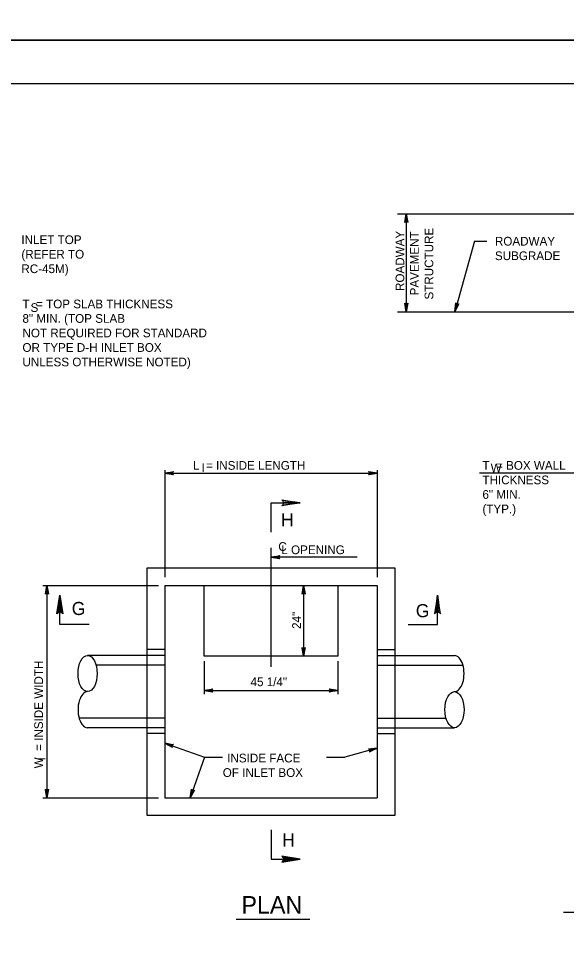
# Model space of a CAD drawing. Extents: x -6420 to 49575, y -4552 to 11624.
# Drawn here: x -5195 to -4576, y 6704 to 7751 of the extents above; entities that cross this region are included whole.
import ezdxf

# ---------------------------------------------------------------- set-up
doc = ezdxf.new("R2010")
doc.units = 0
doc.layers.add('1', color=7, linetype='Continuous')
doc.layers.add('PLT-BNDY', color=7, linetype='Continuous')

msp = doc.modelspace()

# ---------------------------------------------------------------- linework, layer by layer
at = {"layer": '1'}
for p, q in [((-4767, 7530), (-4533.9, 7530)), ((-4757.2, 7530), (-4757.2, 7419.5)), ((-4680.2, 7499.1), (-4702.2, 7419.5)), ((-4680.2, 7499.1), (-4666.2, 7499.1)), ((-4767, 7419.5), (-4533.9, 7419.5)), ((-5030, 7240.2), (-5030, 7119.4)), ((-5030, 7236.9), (-4790, 7236.9)), ((-4790, 7240.2), (-4790, 7119.4)), ((-4674.7, 7237.3), (-4479.3, 7237.3)), ((-4910, 7018), (-4910, 7152.5)), ((-4812.9, 7142), (-4910, 7142)), ((-5167.7, 7110), (-5037.3, 7110)), ((-5163.2, 7110), (-5163.2, 6870)), ((-5030, 7110), (-5030, 6870)), ((-5030, 7110), (-4790, 7110)), ((-4985.5, 7110), (-4834.6, 7110)), ((-4985.5, 7030), (-4985.5, 7110)), ((-4873.2, 7110), (-4873.2, 7030)), ((-4834.6, 7110), (-4834.6, 7030)), ((-4790, 7110), (-4790, 6870)), ((-5030, 7037.5), (-5050, 7037.5)), ((-4790, 7037.5), (-4770, 7037.5)), ((-5050, 7030.8), (-5117.3, 7030.8)), ((-5030, 7030.8), (-5050, 7030.8)), ((-4834.6, 7030), (-4985.5, 7030)), ((-4985.5, 7024.4), (-4985.5, 6987.1)), ((-4834.6, 7024.4), (-4834.6, 6987.1)), ((-4790, 7030.8), (-4770, 7030.8)), ((-4770, 7030.8), (-4702.8, 7030.8)), ((-5030, 7020), (-5107.7, 7020)), ((-4790, 7020), (-4693.2, 7020)), ((-4985.5, 6991.3), (-4834.6, 6991.3)), ((-5030, 6960), (-5126.9, 6960)), ((-4790, 6960), (-4712.3, 6960)), ((-5050, 6949.1), (-5117.3, 6949.1)), ((-5030, 6949.1), (-5050, 6949.1)), ((-5030, 6942.5), (-5050, 6942.5)), ((-4790, 6949.1), (-4770, 6949.1)), ((-4790, 6942.5), (-4770, 6942.5)), ((-4770, 6949.1), (-4702.8, 6949.1)), ((-5030, 6931.7), (-4985.3, 6915.8)), ((-4790, 6926), (-4826.8, 6915.8)), ((-4985.3, 6915.8), (-5001.5, 6870)), ((-4985.3, 6915.8), (-4964.9, 6915.8)), ((-4847.2, 6915.8), (-4826.8, 6915.8)), ((-5167.7, 6870), (-5037.3, 6870)), ((-5030, 6870), (-4790, 6870)), ((-4579.7, 6740.7), (-4459.5, 6740.7)), ((-4949.3, 6732.8), (-4866.2, 6732.8))]:
    msp.add_line(p, q, dxfattribs=at)
for points in [[(-3713.7, 5826.7), (-3713.7, 7677), (-6292.4, 7677), (-6292.4, 5826.7), (-3713.7, 5826.7), (-3713.7, 5913.1), (-4369.8, 5913.1), (-4369.8, 6125.3), (-3713.7, 6125.3), (-3713.7, 6220.4), (-4369.8, 6220.4), (-4369.8, 5826.7), (-4111.3, 5826.7), (-4111.3, 5913.1), (-4111.3, 5826.7), (-3858.7, 5826.7), (-3858.7, 5913.1), (-3858.7, 5872.7), (-3713.7, 5872.7)], [(-4757.2, 7530), (-4755.4, 7520.2), (-4755.9, 7521), (-4756.5, 7521.3), (-4757.2, 7521.5), (-4757.8, 7521.3), (-4758.5, 7521), (-4759, 7520.2), (-4757.2, 7530), (-4758.5, 7521), (-4757.8, 7521.3), (-4757.2, 7530), (-4757.2, 7521.5), (-4756.5, 7521.3), (-4757.2, 7530), (-4755.9, 7521)], [(-4757.2, 7419.5), (-4759, 7429.3), (-4758.5, 7428.6), (-4757.8, 7428.2), (-4757.2, 7428.1), (-4756.5, 7428.2), (-4755.9, 7428.6), (-4755.4, 7429.3), (-4757.2, 7419.5), (-4755.9, 7428.6), (-4756.5, 7428.2), (-4757.2, 7419.5), (-4757.2, 7428.1), (-4757.8, 7428.2), (-4757.2, 7419.5), (-4758.5, 7428.6)], [(-4702.2, 7419.5), (-4701.4, 7429.4), (-4701.1, 7428.6), (-4700.6, 7428), (-4699.9, 7427.7), (-4699.3, 7427.7), (-4698.6, 7427.9), (-4697.8, 7428.5), (-4702.2, 7419.5), (-4698.6, 7427.9), (-4699.3, 7427.7), (-4702.2, 7419.5), (-4699.9, 7427.7), (-4700.6, 7428), (-4702.2, 7419.5), (-4701.1, 7428.6)], [(-5030, 7236.9), (-5020.2, 7238.7), (-5020.6, 7238.5), (-5021, 7238.2), (-5021.2, 7237.9), (-5021.4, 7237.6), (-5021.4, 7237.2), (-5021.5, 7236.9), (-5021.4, 7236.6), (-5021.4, 7236.3), (-5021.2, 7235.9), (-5021, 7235.6), (-5020.6, 7235.3), (-5020.2, 7235.1), (-5030, 7236.9), (-5020.6, 7235.3), (-5021, 7235.6), (-5030, 7236.9), (-5021.2, 7235.9), (-5021.4, 7236.3), (-5030, 7236.9), (-5021.4, 7236.6), (-5021.5, 7236.9), (-5030, 7236.9), (-5021.4, 7237.2), (-5021.4, 7237.6), (-5030, 7236.9), (-5021.2, 7237.9), (-5021, 7238.2), (-5030, 7236.9), (-5020.6, 7238.5)], [(-4790, 7236.9), (-4799.8, 7235.1), (-4799.4, 7235.3), (-4799.1, 7235.6), (-4798.9, 7235.9), (-4798.7, 7236.3), (-4798.6, 7236.6), (-4798.6, 7236.9), (-4798.6, 7237.2), (-4798.7, 7237.6), (-4798.9, 7237.9), (-4799.1, 7238.2), (-4799.4, 7238.5), (-4799.8, 7238.7), (-4790, 7236.9), (-4799.4, 7238.5), (-4799.1, 7238.2), (-4790, 7236.9), (-4798.9, 7237.9), (-4798.7, 7237.6), (-4790, 7236.9), (-4798.6, 7237.2), (-4798.6, 7236.9), (-4790, 7236.9), (-4798.6, 7236.6), (-4798.7, 7236.3), (-4790, 7236.9), (-4798.9, 7235.9), (-4799.1, 7235.6), (-4790, 7236.9), (-4799.4, 7235.3)], [(-4910, 7170.3), (-4910, 7203.4), (-4877, 7203.4)], [(-4897, 7205.9), (-4896.2, 7204.5), (-4877, 7203.4), (-4897, 7205.9), (-4898, 7206.8), (-4877, 7203.4), (-4896.2, 7202.5), (-4896.9, 7201), (-4877, 7203.4), (-4898, 7200.1), (-4896.9, 7201)], [(-4910, 7142), (-4900.2, 7143.8), (-4900.6, 7143.5), (-4901, 7143.3), (-4901.2, 7143), (-4901.4, 7142.6), (-4901.4, 7142.3), (-4901.5, 7142), (-4901.4, 7141.6), (-4901.4, 7141.3), (-4901.2, 7141), (-4901, 7140.7), (-4900.6, 7140.4), (-4900.2, 7140.1), (-4910, 7142), (-4900.6, 7140.4), (-4901, 7140.7), (-4910, 7142), (-4901.2, 7141), (-4901.4, 7141.3), (-4910, 7142), (-4901.4, 7141.6), (-4901.5, 7142), (-4910, 7142), (-4901.4, 7142.3), (-4901.4, 7142.6), (-4910, 7142), (-4901.2, 7143), (-4901, 7143.3), (-4910, 7142), (-4900.6, 7143.5)], [(-5163.2, 7110), (-5161.4, 7100.2), (-5161.6, 7100.6), (-5161.9, 7100.9), (-5162.2, 7101.1), (-5162.6, 7101.3), (-5162.9, 7101.4), (-5163.2, 7101.4), (-5163.5, 7101.4), (-5163.9, 7101.3), (-5164.2, 7101.1), (-5164.5, 7100.9), (-5164.8, 7100.6), (-5165, 7100.2), (-5163.2, 7110), (-5164.8, 7100.6), (-5164.5, 7100.9), (-5163.2, 7110), (-5164.2, 7101.1), (-5163.9, 7101.3), (-5163.2, 7110), (-5163.5, 7101.4), (-5163.2, 7101.4), (-5163.2, 7110), (-5162.9, 7101.4), (-5162.6, 7101.3), (-5163.2, 7110), (-5162.2, 7101.1), (-5161.9, 7100.9), (-5163.2, 7110), (-5161.6, 7100.6)], [(-4873.2, 7110), (-4871.3, 7100.2), (-4871.6, 7100.6), (-4871.8, 7100.9), (-4872.2, 7101.1), (-4872.5, 7101.3), (-4872.8, 7101.4), (-4873.2, 7101.4), (-4873.5, 7101.4), (-4873.8, 7101.3), (-4874.1, 7101.1), (-4874.5, 7100.9), (-4874.7, 7100.6), (-4875, 7100.2), (-4873.2, 7110), (-4874.7, 7100.6), (-4874.5, 7100.9), (-4873.2, 7110), (-4874.1, 7101.1), (-4873.8, 7101.3), (-4873.2, 7110), (-4873.5, 7101.4), (-4873.2, 7101.4), (-4873.2, 7110), (-4872.8, 7101.4), (-4872.5, 7101.3), (-4873.2, 7110), (-4872.2, 7101.1), (-4871.8, 7100.9), (-4873.2, 7110), (-4871.6, 7100.6)], [(-5151.2, 7078.9), (-5149.8, 7079.6), (-5148.7, 7098.9), (-5151.2, 7078.9), (-5152.1, 7077.8), (-5148.7, 7098.9), (-5147.7, 7079.6), (-5146.3, 7078.9), (-5148.7, 7098.9), (-5145.3, 7077.8), (-5146.3, 7078.9)], [(-5115.6, 7065.8), (-5148.7, 7065.8), (-5148.7, 7098.9)], [(-4755.1, 7065.8), (-4722, 7065.8), (-4722, 7098.9)], [(-4719.5, 7078.9), (-4721, 7079.6), (-4722, 7098.9), (-4719.5, 7078.9), (-4718.7, 7077.8), (-4722, 7098.9), (-4723, 7079.6), (-4724.4, 7078.9), (-4722, 7098.9), (-4725.4, 7077.8), (-4724.4, 7078.9)], [(-4873.2, 7030), (-4875, 7039.8), (-4874.7, 7039.4), (-4874.5, 7039), (-4874.1, 7038.8), (-4873.8, 7038.6), (-4873.5, 7038.6), (-4873.2, 7038.5), (-4872.8, 7038.6), (-4872.5, 7038.6), (-4872.2, 7038.8), (-4871.8, 7039), (-4871.6, 7039.4), (-4871.3, 7039.8), (-4873.2, 7030), (-4871.6, 7039.4), (-4871.8, 7039), (-4873.2, 7030), (-4872.2, 7038.8), (-4872.5, 7038.6), (-4873.2, 7030), (-4872.8, 7038.6), (-4873.2, 7038.5), (-4873.2, 7030), (-4873.5, 7038.6), (-4873.8, 7038.6), (-4873.2, 7030), (-4874.1, 7038.8), (-4874.5, 7039), (-4873.2, 7030), (-4874.7, 7039.4)], [(-4985.5, 6991.3), (-4975.7, 6993.1), (-4976, 6992.9), (-4976.4, 6992.6), (-4976.6, 6992.3), (-4976.8, 6992), (-4976.9, 6991.6), (-4976.9, 6991.3), (-4976.9, 6991), (-4976.8, 6990.6), (-4976.6, 6990.3), (-4976.4, 6990), (-4976, 6989.7), (-4975.7, 6989.5), (-4985.5, 6991.3), (-4976, 6989.7), (-4976.4, 6990), (-4985.5, 6991.3), (-4976.6, 6990.3), (-4976.8, 6990.6), (-4985.5, 6991.3), (-4976.9, 6991), (-4976.9, 6991.3), (-4985.5, 6991.3), (-4976.9, 6991.6), (-4976.8, 6992), (-4985.5, 6991.3), (-4976.6, 6992.3), (-4976.4, 6992.6), (-4985.5, 6991.3), (-4976, 6992.9)], [(-4834.6, 6991.3), (-4844.4, 6989.5), (-4844, 6989.7), (-4843.7, 6990), (-4843.5, 6990.3), (-4843.3, 6990.6), (-4843.2, 6991), (-4843.1, 6991.3), (-4843.2, 6991.6), (-4843.3, 6992), (-4843.5, 6992.3), (-4843.7, 6992.6), (-4844, 6992.9), (-4844.4, 6993.1), (-4834.6, 6991.3), (-4844, 6992.9), (-4843.7, 6992.6), (-4834.6, 6991.3), (-4843.5, 6992.3), (-4843.3, 6992), (-4834.6, 6991.3), (-4843.2, 6991.6), (-4843.1, 6991.3), (-4834.6, 6991.3), (-4843.2, 6991), (-4843.3, 6990.6), (-4834.6, 6991.3), (-4843.5, 6990.3), (-4843.7, 6990), (-4834.6, 6991.3), (-4844, 6989.7)], [(-5030, 6931.7), (-5020.2, 6930.2), (-5020.6, 6930.1), (-5021.1, 6929.9), (-5021.4, 6929.7), (-5021.7, 6929.4), (-5021.8, 6929.2), (-5022, 6928.9), (-5022.1, 6928.5), (-5022.1, 6928.2), (-5022, 6927.8), (-5022, 6927.5), (-5021.7, 6927.1), (-5021.4, 6926.7), (-5030, 6931.7), (-5021.7, 6927.1), (-5022, 6927.5), (-5030, 6931.7), (-5022, 6927.8), (-5022.1, 6928.2), (-5030, 6931.7), (-5022.1, 6928.5), (-5022, 6928.9), (-5030, 6931.7), (-5021.8, 6929.2), (-5021.7, 6929.4), (-5030, 6931.7), (-5021.4, 6929.7), (-5021.1, 6929.9), (-5030, 6931.7), (-5020.6, 6930.1)], [(-4790, 6926), (-4799, 6921.7), (-4798.7, 6922), (-4798.4, 6922.4), (-4798.3, 6922.7), (-4798.2, 6923.1), (-4798.2, 6923.4), (-4798.3, 6923.8), (-4798.4, 6924.1), (-4798.5, 6924.4), (-4798.8, 6924.6), (-4799.1, 6924.9), (-4799.5, 6925), (-4800, 6925.2), (-4790, 6926), (-4799.5, 6925), (-4799.1, 6924.9), (-4790, 6926), (-4798.8, 6924.6), (-4798.5, 6924.4), (-4790, 6926), (-4798.4, 6924.1), (-4798.3, 6923.8), (-4790, 6926), (-4798.2, 6923.4), (-4798.2, 6923.1), (-4790, 6926), (-4798.3, 6922.7), (-4798.4, 6922.4), (-4790, 6926), (-4798.7, 6922)], [(-5163.2, 6870), (-5165, 6879.8), (-5164.8, 6879.4), (-5164.5, 6879), (-5164.2, 6878.8), (-5163.9, 6878.6), (-5163.5, 6878.6), (-5163.2, 6878.5), (-5162.9, 6878.6), (-5162.6, 6878.6), (-5162.2, 6878.8), (-5161.9, 6879), (-5161.6, 6879.4), (-5161.4, 6879.8), (-5163.2, 6870), (-5161.6, 6879.4), (-5161.9, 6879), (-5163.2, 6870), (-5162.2, 6878.8), (-5162.6, 6878.6), (-5163.2, 6870), (-5162.9, 6878.6), (-5163.2, 6878.5), (-5163.2, 6870), (-5163.5, 6878.6), (-5163.9, 6878.6), (-5163.2, 6870), (-5164.2, 6878.8), (-5164.5, 6879), (-5163.2, 6870), (-5164.8, 6879.4)], [(-5001.5, 6870), (-5000, 6879.8), (-4999.8, 6879.4), (-4999.7, 6878.9), (-4999.5, 6878.6), (-4999.2, 6878.3), (-4998.9, 6878.2), (-4998.6, 6878), (-4998.3, 6878), (-4998, 6877.9), (-4997.6, 6878), (-4997.2, 6878.1), (-4996.9, 6878.3), (-4996.5, 6878.6), (-5001.5, 6870), (-4996.9, 6878.3), (-4997.2, 6878.1), (-5001.5, 6870), (-4997.6, 6878), (-4998, 6877.9), (-5001.5, 6870), (-4998.3, 6878), (-4998.6, 6878), (-5001.5, 6870), (-4998.9, 6878.2), (-4999.2, 6878.3), (-5001.5, 6870), (-4999.5, 6878.6), (-4999.7, 6878.9), (-5001.5, 6870), (-4999.8, 6879.4)], [(-4910, 6833.7), (-4910, 6800.6), (-4877, 6800.6)], [(-4897, 6798.1), (-4896.2, 6799.6), (-4877, 6800.6), (-4897, 6798.1), (-4898, 6797.2), (-4877, 6800.6), (-4896.2, 6801.6), (-4896.9, 6803), (-4877, 6800.6), (-4898, 6804), (-4896.9, 6803)]]:
    msp.add_lwpolyline(points, dxfattribs=at)
msp.add_lwpolyline([(-5050, 7130), (-4770, 7130), (-4770, 6850), (-5050, 6850)], close=True, dxfattribs=at)
for centre, major_axis in [((-5117.3, 7010.4), (0, 20.4)), ((-4702.8, 6969.6), (0, -20.4))]:
    msp.add_ellipse(centre, major_axis=major_axis, ratio=0.531159, dxfattribs=at)
for centre, major_axis in [((-4702.8, 7010.4), (0, -20.4)), ((-5117.3, 6969.6), (0, 20.4))]:
    msp.add_ellipse(centre, major_axis=major_axis, ratio=0.531159, start_param=0, end_param=3.141593, dxfattribs=at)
at = {"layer": 'PLT-BNDY'}
for points in [[(-6420.4, 9675.1), (-3661.2, 9675.1), (-3661.2, 7726.3), (-6420.4, 7726.3)], [(-6420.4, 7726.3), (-3661.2, 7726.3), (-3661.2, 5777.4), (-6420.4, 5777.4)]]:
    msp.add_lwpolyline(points, close=True, dxfattribs=at)

# ---------------------------------------------------------------- texts
at = {"layer": '1'}
for s, height, p in [('INLET TOP', 9.84, (-5192.1, 7495.9)), ('ROADWAY', 9.84, (-4657.1, 7494.2)), ('(REFER TO', 9.84, (-5192.1, 7479.5)), ('SUBGRADE', 9.84, (-4657.1, 7477.8)), ('RC-45M)', 9.84, (-5192.1, 7463.1)), ('T  = TOP SLAB THICKNESS', 9.843, (-5190.9, 7423.3)), ('S', 9.84, (-5181.8, 7419.2)), ('8" MIN. (TOP SLAB', 9.843, (-5190.9, 7406.9)), ('NOT REQUIRED FOR STANDARD', 9.843, (-5190.9, 7390.5)), ('OR TYPE D-H INLET BOX', 9.843, (-5190.9, 7374.1)), ('UNLESS OTHERWISE NOTED)', 9.843, (-5190.9, 7357.7)), ('L  = INSIDE LENGTH', 9.843, (-4998.2, 7240.8)), ('I', 9.84, (-4988.6, 7238.3)), ('T  = BOX WALL', 9.843, (-4671.2, 7240.8)), ('W', 9.84, (-4661.9, 7238)), ('THICKNESS', 9.84, (-4671.2, 7224.4)), ('6" MIN.', 9.84, (-4671.2, 7208)), ('(TYP.)', 9.84, (-4671.2, 7191.6)), ('H', 14.8, (-4898.8, 7176.9)), ('C', 9.84, (-4901.8, 7149.1)), ('L OPENING', 9.84, (-4898.4, 7145.4)), ('G', 14.8, (-5135.2, 7076.6)), ('G', 14.8, (-4746.5, 7074.1)), ('45 1/4"', 9.84, (-4933.2, 6996.2)), ('INSIDE FACE', 9.843, (-4959.6, 6910)), ('OF INLET BOX', 9.843, (-4964.6, 6893.6)), ('H', 14.8, (-4897.5, 6814.9)), ('PLAN', 19.69, (-4943.5, 6739.2))]:
    msp.add_text(s, height=height, dxfattribs=at).set_placement(p)
for s, height, p in [('ROADWAY', 9.84, (-4759.5, 7442.9)), ('PAVEMENT', 9.84, (-4743.1, 7437.9)), ('STRUCTURE', 9.84, (-4726.7, 7433.2)), ('24"', 9.84, (-4876.3, 7060.9)), ('W  = INSIDE WIDTH', 9.843, (-5167.7, 6903.3)), ('I', 9.84, (-5165, 6912.3))]:
    msp.add_text(s, height=height, rotation=90, dxfattribs=at).set_placement(p)

doc.saveas('drawing.dxf')
